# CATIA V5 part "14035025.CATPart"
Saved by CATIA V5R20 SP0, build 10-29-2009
Part number: 14035025
Definition: NONE
Nomenclature: 14035025
Source: Unknown
Description: 14035025
Bounding box of the stored display mesh (mm): x -12.5 to 50, y -31.5 to 21.6, z -21.6 to 21.6
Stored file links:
  C:\Users\Utente\Desktop\IO LAVORO\3D X SITO CF\X SITO\PLASTICA\RF2\14035025.CATPart
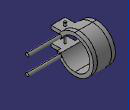
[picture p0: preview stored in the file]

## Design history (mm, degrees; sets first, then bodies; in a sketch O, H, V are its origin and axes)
Body1 "14035025" (main body)
  Solid1: solid without history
